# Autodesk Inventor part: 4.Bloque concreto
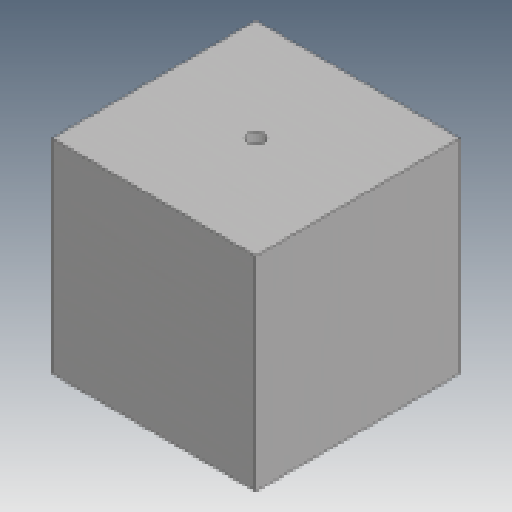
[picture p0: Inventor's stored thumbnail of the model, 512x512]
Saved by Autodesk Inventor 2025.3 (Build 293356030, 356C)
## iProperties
Created: 2025-10
Part Number: 4.Bloque concreto
Material: Genérico
Document SubType Name: Chapa
Designer: User
Density: 1 g/cm^3
Appearance: Valor por defecto
Sheet Metal Rule: Por defecto
Author: User
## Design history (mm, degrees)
sketch "Boceto1"
  geometry: L1 (-236.716, 238.346)-(13.284, 238.346); L2 (13.284, 238.346)-(13.284, -11.654); L3 (13.284, -11.654)-(-236.716, -11.654); L4 (-236.716, -11.654)-(-236.716, 238.346); 1 further point
  constraints: 8 end point, 2 parallel, 1 horizontal, 1 perpendicular
  dimensions: "d0" = 11.65406 distance from line of L3 point (0, 0); "d1" = 13.284 distance from line of L2 point (0, 0); "d2" = 250 distance of L1.end L2.end; "d3" = 250 distance of L2.end L3.end
extrude "Extrusión1" new body sketch "Boceto1" stored distance "d4" = 250; taper "d5" = 0 deg
sketch "Boceto2"
  geometry: L1 (250, 0)-(0, 0) reference; L2 (0, 250)-(0, 0) reference; 3 further points
  constraints: 1 midpoint
  dimensions: "d6" = 125 distance from line of L1 point (125, 125); "d7" = 125 distance of point (0, 125) point (125, 125)
hole "Agujero1" sketch "Boceto2" at (125, 125) diameter "d8" = 20; stored, may be unused: countersink angle "d12" = 90 deg, drill point angle "d14" = 0 deg; dims "d9" = 24, "d10" = 4, "d11" = 2, "d13" = 150
node "Sólido1"
node "Acabados"
node "Finish1" dims "Finish1_Area" = 38442.4778
other parameters: "Grosor" = 3.048 (derived), "FactorK" = 4.4, "Radio_pliegue" = 3.048 (= Grosor), "Anchura_desahogo_plegado" = 3.048 (= Grosor), "Profundidad_desahogo_plegado" = 1.524 (= 0.5 x Grosor), "Tamaño_destalonado" = 12.192 (= 4 x Grosor), "Separación_entre_unión" = 0.01, "Remanente_mínimo" = 6.096 (= 2 x Grosor), "Radiodetransición" = 3.048 (= Radio_pliegue), "Tamaño_de_radio_de_Jacobi" = 3.048 (= Radio_pliegue), "TamañoSeparación" = 3.048 (= Grosor)
